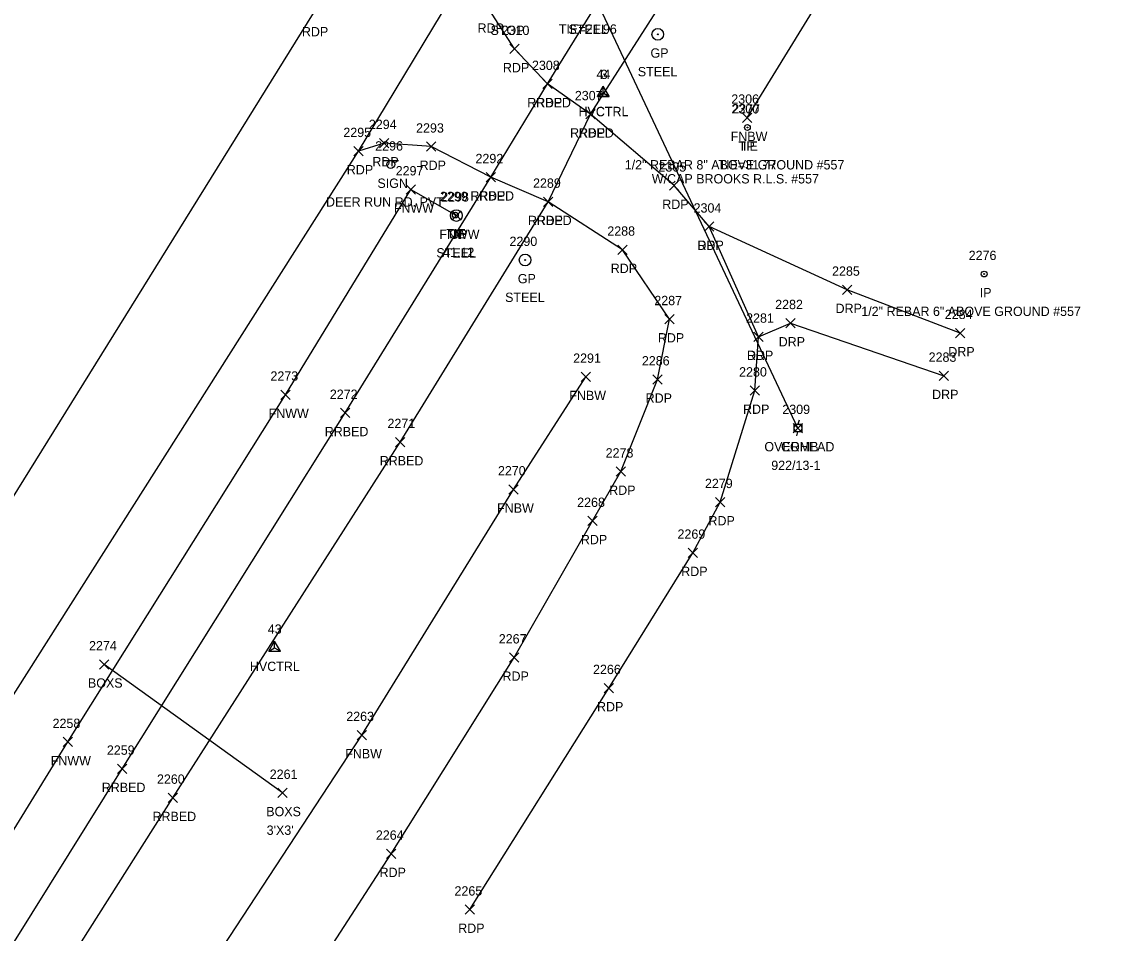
# Model space of a CAD drawing. Extents: x 1508122 to 1515053, y 865012 to 875267.
# Drawn here: x 1513728.5 to 1513963.5, y 873540.6 to 873736 of the extents above; entities that cross this region are included whole.
import ezdxf

# ---------------------------------------------------------------- set-up
doc = ezdxf.new("R2010")
doc.units = 0
for name, color, linetype in [('C_A', 7, 'Continuous'), ('C_C', 7, 'Continuous'), ('C_I', 7, 'Continuous'), ('CBP', 7, 'Continuous'), ('CPSM', 7, 'Continuous'), ('D_A', 7, 'Continuous'), ('D_C', 7, 'Continuous'), ('D_I', 7, 'Continuous'), ('D_TIC', 7, 'Continuous'), ('DDEFAULT', 7, 'Continuous'), ('L_A', 7, 'Continuous'), ('L_I', 7, 'Continuous'), ('L_TIC', 7, 'Continuous'), ('LFNC', 7, 'Continuous'), ('M_A', 7, 'Continuous'), ('M_C', 7, 'Continuous'), ('M_I', 7, 'Continuous'), ('MPIR', 7, 'Continuous'), ('P_A', 7, 'Continuous'), ('P_I', 7, 'Continuous'), ('P_TIC', 7, 'Continuous'), ('PET', 7, 'Continuous'), ('R_A', 7, 'Continuous'), ('R_C', 7, 'Continuous'), ('R_I', 7, 'Continuous'), ('R_TIC', 7, 'Continuous'), ('RDP', 7, 'Continuous'), ('RGP', 7, 'Continuous'), ('RRB', 7, 'Continuous'), ('S_A', 7, 'Continuous'), ('S_C', 7, 'Continuous'), ('S_I', 7, 'Continuous'), ('SSGN', 7, 'Continuous'), ('U_A', 7, 'Continuous'), ('U_C', 7, 'Continuous'), ('U_I', 7, 'Continuous'), ('U_TIC', 7, 'Continuous'), ('UP', 7, 'Continuous'), ('UT', 7, 'Continuous')]:
    doc.layers.add(name, color=color, linetype=linetype)

msp = doc.modelspace()

# ---------------------------------------------------------------- linework, layer by layer
at = {"layer": 'CBP'}
for centre, radius in [((1513884.03, 873713.34), 0.625), ((1513884.03, 873713.34), 0.0833), ((1513821.41, 873694.56), 0.625), ((1513821.41, 873694.56), 0.0833)]:
    msp.add_circle(centre, radius, dxfattribs=at)
at = {"layer": 'CPSM'}
for p, q in [((1513851.88, 873720.05), (1513853.13, 873722.21)), ((1513851.88, 873720.01), (1513853.13, 873722.18)), ((1513854.38, 873720.05), (1513853.13, 873722.21)), ((1513853.13, 873720.77), (1513853.13, 873722.21)), ((1513854.38, 873720.01), (1513853.13, 873722.18)), ((1513853.13, 873720.73), (1513853.13, 873722.18)), ((1513851.88, 873720.05), (1513853.13, 873720.77)), ((1513851.88, 873720.01), (1513853.13, 873720.73)), ((1513851.88, 873720.05), (1513854.38, 873720.05)), ((1513851.88, 873720.01), (1513854.38, 873720.01)), ((1513853.13, 873720.77), (1513853.13, 873720.77)), ((1513853.13, 873720.77), (1513854.38, 873720.05)), ((1513853.13, 873720.73), (1513853.13, 873720.73)), ((1513853.13, 873720.73), (1513854.38, 873720.01)), ((1513781.42, 873601.07), (1513782.67, 873603.23)), ((1513783.92, 873601.07), (1513782.67, 873603.23)), ((1513782.67, 873601.79), (1513782.67, 873603.23)), ((1513781.42, 873601.07), (1513782.67, 873601.79)), ((1513781.42, 873601.07), (1513783.92, 873601.07)), ((1513782.67, 873601.79), (1513782.67, 873601.79)), ((1513782.67, 873601.79), (1513783.92, 873601.07))]:
    msp.add_line(p, q, dxfattribs=at)
at = {"layer": 'D_TIC'}
for points in [[(1513745.14, 873597.23), (1513747.14, 873599.23)], [(1513747.14, 873597.23), (1513745.14, 873599.23)], [(1513783.36, 873569.67), (1513785.36, 873571.67)], [(1513785.36, 873569.67), (1513783.36, 873571.67)]]:
    msp.add_lwpolyline(points, dxfattribs=at)
at = {"layer": 'DDEFAULT'}
msp.add_lwpolyline([(1513784.36, 873570.67), (1513746.14, 873598.23)], dxfattribs=at)
at = {"layer": 'L_TIC'}
for points in [[(1513882.96, 873714.43), (1513884.96, 873716.43)], [(1513884.96, 873714.43), (1513882.96, 873716.43)], [(1513810.88, 873699.06), (1513812.88, 873701.06)], [(1513812.88, 873699.06), (1513810.88, 873701.06)], [(1513820.63, 873693.46), (1513822.63, 873695.46)], [(1513822.63, 873693.46), (1513820.63, 873695.46)], [(1513848.36, 873658.88), (1513850.36, 873660.88)], [(1513850.36, 873658.88), (1513848.36, 873660.88)], [(1513784.03, 873655.05), (1513786.03, 873657.05)], [(1513786.03, 873655.05), (1513784.03, 873657.05)], [(1513832.88, 873634.74), (1513834.88, 873636.74)], [(1513834.88, 873634.74), (1513832.88, 873636.74)], [(1513800.33, 873582.07), (1513802.33, 873584.07)], [(1513802.33, 873582.07), (1513800.33, 873584.07)], [(1513737.32, 873580.58), (1513739.32, 873582.58)], [(1513739.32, 873580.58), (1513737.32, 873582.58)]]:
    msp.add_lwpolyline(points, dxfattribs=at)
at = {"layer": 'LFNC'}
for points in [[(1513883.96, 873715.43), (1513940.11, 873806.81), (1513990.41, 873887.15)], [(1513218.01, 872682.67), (1513239.79, 872733.41), (1513260.59, 872779.32), (1513279.8, 872820.34), (1513309.34, 872879.26), (1513337.46, 872931.88), (1513364.68, 872976.76), (1513384.37, 873008.89), (1513425.94, 873076.78), (1513474.35, 873155.62), (1513492.34, 873185.42), (1513532.61, 873250.79), (1513565.82, 873304.9), (1513599.41, 873358.19), (1513608.93, 873372.42), (1513641.55, 873425.64), (1513687.17, 873499.06), (1513712.19, 873539.19), (1513738.32, 873581.58), (1513785.03, 873656.05), (1513811.88, 873700.06), (1513821.63, 873694.46)], [(1513422.18, 872973.96), (1513469.32, 873050.55), (1513492.37, 873088.08), (1513518.11, 873128.09), (1513536.42, 873156.9), (1513559.84, 873194.99), (1513607.97, 873274.08), (1513649.94, 873340.43), (1513686.06, 873398.91), (1513733.34, 873474.67), (1513756.79, 873511.95), (1513770.19, 873535.54), (1513801.33, 873583.07), (1513833.88, 873635.74), (1513849.36, 873659.88)]]:
    msp.add_lwpolyline(points, dxfattribs=at)
at = {"layer": 'MPIR'}
for centre, radius in [((1513884.03, 873713.34), 0.625), ((1513884.03, 873713.34), 0.0833), ((1513934.79, 873681.92), 0.625), ((1513934.79, 873681.92), 0.0833)]:
    msp.add_circle(centre, radius, dxfattribs=at)
at = {"layer": 'P_TIC'}
for points in [[(1513833.12, 873729.17), (1513835.12, 873731.17)], [(1513835.12, 873729.17), (1513833.12, 873731.17)], [(1513840.18, 873721.67), (1513842.18, 873723.67)], [(1513842.18, 873721.67), (1513840.18, 873723.67)], [(1513849.37, 873715.18), (1513851.37, 873717.18)], [(1513851.37, 873715.18), (1513849.37, 873717.18)], [(1513805.13, 873709), (1513807.13, 873711)], [(1513807.13, 873709), (1513805.13, 873711)], [(1513815.26, 873708.24), (1513817.26, 873710.24)], [(1513817.26, 873708.24), (1513815.26, 873710.24)], [(1513799.66, 873707.29), (1513801.66, 873709.29)], [(1513801.66, 873707.29), (1513799.66, 873709.29)], [(1513799.66, 873707.29), (1513801.66, 873709.29)], [(1513801.66, 873707.29), (1513799.66, 873709.29)], [(1513827.99, 873701.68), (1513829.99, 873703.68)], [(1513829.99, 873701.68), (1513827.99, 873703.68)], [(1513867.29, 873699.88), (1513869.29, 873701.88)], [(1513869.29, 873699.88), (1513867.29, 873701.88)], [(1513840.33, 873696.41), (1513842.33, 873698.41)], [(1513842.33, 873696.41), (1513840.33, 873698.41)], [(1513874.83, 873691.09), (1513876.83, 873693.09)], [(1513876.83, 873691.09), (1513874.83, 873693.09)], [(1513856.25, 873686.14), (1513858.25, 873688.14)], [(1513858.25, 873686.14), (1513856.25, 873688.14)], [(1513866.33, 873671.24), (1513868.33, 873673.24)], [(1513868.33, 873671.24), (1513866.33, 873673.24)], [(1513885.44, 873667.48), (1513887.44, 873669.48)], [(1513887.44, 873667.48), (1513885.44, 873669.48)], [(1513863.72, 873658.32), (1513865.72, 873660.32)], [(1513865.72, 873658.32), (1513863.72, 873660.32)], [(1513884.6, 873655.94), (1513886.6, 873657.94)], [(1513886.6, 873655.94), (1513884.6, 873657.94)], [(1513855.9, 873638.57), (1513857.9, 873640.57)], [(1513857.9, 873638.57), (1513855.9, 873640.57)], [(1513877.19, 873632.02), (1513879.19, 873634.02)], [(1513879.19, 873632.02), (1513877.19, 873634.02)], [(1513849.83, 873627.98), (1513851.83, 873629.98)], [(1513851.83, 873627.98), (1513849.83, 873629.98)], [(1513871.35, 873621.16), (1513873.35, 873623.16)], [(1513873.35, 873621.16), (1513871.35, 873623.16)], [(1513833.03, 873598.7), (1513835.03, 873600.7)], [(1513835.03, 873598.7), (1513833.03, 873600.7)], [(1513853.29, 873592.15), (1513855.29, 873594.15)], [(1513855.29, 873592.15), (1513853.29, 873594.15)], [(1513806.68, 873556.62), (1513808.68, 873558.62)], [(1513808.68, 873556.62), (1513806.68, 873558.62)], [(1513823.54, 873544.65), (1513825.54, 873546.65)], [(1513825.54, 873544.65), (1513823.54, 873546.65)]]:
    msp.add_lwpolyline(points, dxfattribs=at)
at = {"layer": 'PET'}
for points in [[(1513466.17, 873213.07), (1513500.31, 873271.08), (1513533.51, 873325.85), (1513565.92, 873377.51), (1513601.02, 873434.43), (1513630.8, 873481.59), (1513663.12, 873532.69), (1513695.04, 873583.32), (1513791.03, 873737.88), (1513811.04, 873770.52), (1513826.41, 873795.21), (1513862.7, 873855.82), (1513892.11, 873904.49), (1513923.1, 873954.81)], [(1513455.04, 873151.27), (1513485.29, 873202.33), (1513519.6, 873259.87), (1513551.9, 873312.77), (1513584.37, 873365.63), (1513617.09, 873418.81), (1513648.76, 873468.83), (1513681.49, 873520.59), (1513713.49, 873570.94), (1513800.66, 873708.29), (1513826.54, 873751.18), (1513852.76, 873793.88), (1513881.72, 873842.17), (1513911.67, 873891.89), (1513942.82, 873942.89)], [(1513824.54, 873545.65), (1513854.29, 873593.15), (1513872.35, 873622.16), (1513878.19, 873633.02), (1513885.6, 873656.94), (1513886.44, 873668.48), (1513875.83, 873692.09), (1513868.29, 873700.88), (1513850.37, 873716.18), (1513841.18, 873722.67), (1513834.12, 873730.17), (1513828.68, 873738.66), (1513826.54, 873751.18)], [(1513618.36, 873267.88), (1513664.43, 873331.28), (1513701.45, 873388.1), (1513749.56, 873465.53), (1513781.18, 873516.7), (1513807.68, 873557.62), (1513834.03, 873599.7), (1513850.83, 873628.98), (1513856.9, 873639.57), (1513864.72, 873659.32), (1513867.33, 873672.24), (1513857.25, 873687.14), (1513841.33, 873697.41), (1513828.99, 873702.68), (1513816.26, 873709.24), (1513806.13, 873710), (1513800.66, 873708.29)]]:
    msp.add_lwpolyline(points, dxfattribs=at)
at = {"layer": 'R_TIC'}
for points in [[(1513840.18, 873721.67), (1513842.18, 873723.67)], [(1513842.18, 873721.67), (1513840.18, 873723.67)], [(1513849.37, 873715.18), (1513851.37, 873717.18)], [(1513851.37, 873715.18), (1513849.37, 873717.18)], [(1513827.99, 873701.68), (1513829.99, 873703.68)], [(1513829.99, 873701.68), (1513827.99, 873703.68)], [(1513840.33, 873696.41), (1513842.33, 873698.41)], [(1513842.33, 873696.41), (1513840.33, 873698.41)], [(1513874.83, 873691.09), (1513876.83, 873693.09)], [(1513876.83, 873691.09), (1513874.83, 873693.09)], [(1513904.44, 873677.55), (1513906.44, 873679.55)], [(1513906.44, 873677.55), (1513904.44, 873679.55)], [(1513892.24, 873670.39), (1513894.24, 873672.39)], [(1513894.24, 873670.39), (1513892.24, 873672.39)], [(1513928.61, 873668.27), (1513930.61, 873670.27)], [(1513930.61, 873668.27), (1513928.61, 873670.27)], [(1513885.44, 873667.48), (1513887.44, 873669.48)], [(1513887.44, 873667.48), (1513885.44, 873669.48)], [(1513925.14, 873659.1), (1513927.14, 873661.1)], [(1513927.14, 873659.1), (1513925.14, 873661.1)], [(1513796.76, 873651.14), (1513798.76, 873653.14)], [(1513798.76, 873651.14), (1513796.76, 873653.14)], [(1513808.55, 873644.89), (1513810.55, 873646.89)], [(1513810.55, 873644.89), (1513808.55, 873646.89)], [(1513748.97, 873574.84), (1513750.97, 873576.84)], [(1513750.97, 873574.84), (1513748.97, 873576.84)], [(1513759.83, 873568.62), (1513761.83, 873570.62)], [(1513761.83, 873568.62), (1513759.83, 873570.62)]]:
    msp.add_lwpolyline(points, dxfattribs=at)
at = {"layer": 'RDP'}
for points in [[(1513929.61, 873669.27), (1513905.44, 873678.55), (1513875.83, 873692.09)], [(1513886.44, 873668.48), (1513893.24, 873671.39), (1513926.14, 873660.1)]]:
    msp.add_lwpolyline(points, dxfattribs=at)
at = {"layer": 'RGP'}
for p, q in [((1513864.82, 873733.31), (1513864.82, 873733.31)), ((1513821.63, 873694.46), (1513821.63, 873694.46)), ((1513836.37, 873684.93), (1513836.37, 873684.93))]:
    msp.add_line(p, q, dxfattribs=at)
for centre, radius in [((1513864.82, 873733.31), 1.25), ((1513864.82, 873733.31), 0.0833), ((1513821.63, 873694.46), 1.25), ((1513821.63, 873694.46), 0.0833), ((1513836.37, 873684.93), 1.25), ((1513836.37, 873684.93), 0.0833)]:
    msp.add_circle(centre, radius, dxfattribs=at)
at = {"layer": 'RRB'}
for points in [[(1513228.31, 872677.99), (1513247.91, 872725.05), (1513270.86, 872775.34), (1513289.12, 872813.81), (1513319.1, 872873.87), (1513347.47, 872925.52), (1513374.77, 872971.44), (1513393.49, 873000.11), (1513437.27, 873071.02), (1513458.13, 873103.89), (1513504.32, 873179.38), (1513525.85, 873213.8), (1513574, 873293.73), (1513619.17, 873366.93), (1513650.95, 873417.63), (1513697.43, 873492.91), (1513723.07, 873532.74), (1513749.97, 873575.84), (1513797.76, 873652.14), (1513828.99, 873702.68), (1513841.18, 873722.67), (1513905.39, 873826.67), (1513957.69, 873911.9), (1513997.47, 873975.73)], [(1513240.34, 872672.59), (1513259.24, 872718.12), (1513282.12, 872769.92), (1513300.61, 872809.77), (1513331.29, 872869.64), (1513358.47, 872918.38), (1513387.89, 872964.97), (1513404.26, 872991.91), (1513448.93, 873064.4), (1513469.17, 873096.67), (1513514.98, 873172.69), (1513538.39, 873208.28), (1513585.22, 873287.66), (1513630.12, 873359.27), (1513661.28, 873410.15), (1513709.31, 873487.04), (1513733.32, 873526.23), (1513760.83, 873569.62), (1513809.55, 873645.89), (1513841.33, 873697.41), (1513850.37, 873716.18), (1513916.81, 873819.88), (1513968.56, 873904.51), (1514007.95, 873968.59)]]:
    msp.add_lwpolyline(points, dxfattribs=at)
at = {"layer": 'SSGN'}
for p, q in [((1513805.92, 873706.25), (1513809.25, 873706.25)), ((1513807.57, 873705.41), (1513807.57, 873705.41))]:
    msp.add_line(p, q, dxfattribs=at)
msp.add_circle((1513807.57, 873705.41), 0.833, dxfattribs=at)
at = {"layer": 'U_TIC'}
for points in [[(1513893.86, 873647.9), (1513895.86, 873649.9)], [(1513895.86, 873647.9), (1513893.86, 873649.9)]]:
    msp.add_lwpolyline(points, dxfattribs=at)
at = {"layer": 'UP'}
for p, q in [((1513894.02, 873648.07), (1513894.02, 873649.73)), ((1513894.02, 873649.73), (1513895.69, 873649.73)), ((1513895.11, 873650.57), (1513894.86, 873649.73)), ((1513895.69, 873649.73), (1513895.69, 873648.07)), ((1513895.69, 873648.07), (1513894.02, 873648.07)), ((1513894.61, 873647.23), (1513894.86, 873648.07)), ((1513894.86, 873648.9), (1513894.86, 873648.9))]:
    msp.add_line(p, q, dxfattribs=at)
msp.add_circle((1513894.86, 873648.9), 0.833, dxfattribs=at)
at = {"layer": 'UT'}
msp.add_lwpolyline([(1513894.86, 873648.9), (1513821.97, 873803.81)], dxfattribs=at)

# ---------------------------------------------------------------- texts
at = {"layer": 'C_A'}
for s, p in [('HVCTRL', (1513847.82, 873715.77)), ('HVCTRL', (1513847.82, 873715.73)), ('TIE', (1513882.11, 873708.34)), ('TIE', (1513819.49, 873689.56)), ('HVCTRL', (1513777.36, 873596.79))]:
    msp.add_text(s, height=2, dxfattribs=at).set_placement(p)
at = {"layer": 'C_C'}
for s, p in [('TIE=21.96', (1513843.61, 873733.45)), ('TIE=31.77', (1513877.82, 873704.34)), ('41.12', (1513818.79, 873685.56))]:
    msp.add_text(s, height=2, dxfattribs=at).set_placement(p)
at = {"layer": 'C_I'}
for s, p in [('44', (1513851.67, 873723.77)), ('3', (1513852.56, 873723.73)), ('2300', (1513880.6, 873716.34)), ('2299', (1513818.14, 873697.56)), ('43', (1513781.2, 873604.79))]:
    msp.add_text(s, height=2, dxfattribs=at).set_placement(p)
at = {"layer": 'D_A'}
for p in [(1513742.64, 873593.23), (1513780.87, 873565.67)]:
    msp.add_text('BOXS', height=2, dxfattribs=at).set_placement(p)
at = {"layer": 'D_C'}
msp.add_text("3'X3'", height=2, dxfattribs=at).set_placement((1513780.96, 873561.67))
at = {"layer": 'D_I'}
for s, p in [('2274', (1513742.88, 873601.23)), ('2261', (1513781.62, 873573.67))]:
    msp.add_text(s, height=2, dxfattribs=at).set_placement(p)
at = {"layer": 'L_A'}
for s, p in [('FNBW', (1513880.44, 873710.43)), ('FNWW', (1513808.23, 873695.06)), ('FNWW', (1513817.98, 873689.46)), ('FNBW', (1513845.84, 873654.88)), ('FNWW', (1513781.38, 873651.05)), ('FNBW', (1513830.36, 873630.74)), ('FNWW', (1513734.67, 873576.58)), ('FNBW', (1513797.8, 873578.07))]:
    msp.add_text(s, height=2, dxfattribs=at).set_placement(p)
at = {"layer": 'L_I'}
for s, p in [('2306', (1513880.57, 873718.43)), ('2297', (1513808.62, 873703.06)), ('2298', (1513818.37, 873697.46)), ('2291', (1513846.67, 873662.88)), ('2273', (1513781.77, 873659.05)), ('2270', (1513830.54, 873638.74)), ('2263', (1513798.02, 873586.07)), ('2258', (1513735.06, 873584.58))]:
    msp.add_text(s, height=2, dxfattribs=at).set_placement(p)
at = {"layer": 'M_A'}
for p in [(1513883.08, 873708.34), (1513933.84, 873676.92)]:
    msp.add_text('IP', height=2, dxfattribs=at).set_placement(p)
at = {"layer": 'M_C'}
for s, p in [('1/2" REBAR 8" ABOVE GROUND #557', (1513857.73, 873704.34)), ('W/CAP BROOKS R.L.S. #557', (1513863.54, 873701.34)), ('1/2" REBAR 6" ABOVE GROUND #557', (1513908.44, 873672.92))]:
    msp.add_text(s, height=2, dxfattribs=at).set_placement(p)
at = {"layer": 'M_I'}
for s, p in [('2277', (1513880.77, 873716.34)), ('2276', (1513931.47, 873684.92))]:
    msp.add_text(s, height=2, dxfattribs=at).set_placement(p)
at = {"layer": 'P_A'}
for p in [(1513788.52, 873732.88), (1513826.17, 873733.66), (1513831.61, 873725.17), (1513838.67, 873717.67), (1513847.86, 873711.18), (1513803.62, 873705), (1513813.75, 873704.24), (1513798.14, 873703.29), (1513798.14, 873703.29), (1513826.47, 873697.68), (1513865.78, 873695.88), (1513838.82, 873692.41), (1513873.31, 873687.09), (1513854.73, 873682.14), (1513864.82, 873667.24), (1513883.93, 873663.48), (1513862.21, 873654.32), (1513883.09, 873651.94), (1513854.39, 873634.57), (1513875.68, 873628.02), (1513848.32, 873623.98), (1513869.84, 873617.16), (1513831.52, 873594.7), (1513851.78, 873588.15), (1513805.17, 873552.62), (1513822.02, 873540.65)]:
    msp.add_text('RDP', height=2, dxfattribs=at).set_placement(p)
at = {"layer": 'P_I'}
for s, p in [('2310', (1513831.34, 873733.17)), ('2308', (1513837.84, 873725.67)), ('2307', (1513847.03, 873719.18)), ('2294', (1513802.87, 873713)), ('2295', (1513797.4, 873711.29)), ('2295', (1513797.4, 873711.29)), ('2293', (1513813, 873712.24)), ('2292', (1513825.73, 873705.68)), ('2305', (1513864.96, 873703.88)), ('2289', (1513838.07, 873700.41)), ('2304', (1513872.49, 873695.09)), ('2288', (1513853.99, 873690.14)), ('2287', (1513864.07, 873675.24)), ('2281', (1513883.75, 873671.48)), ('2286', (1513861.4, 873662.32)), ('2280', (1513882.25, 873659.94)), ('2278', (1513853.64, 873642.57)), ('2279', (1513874.92, 873636.02)), ('2268', (1513847.53, 873631.98)), ('2269', (1513869.04, 873625.16)), ('2267', (1513830.72, 873602.7)), ('2266', (1513850.93, 873596.15)), ('2264', (1513804.37, 873560.62)), ('2265', (1513821.23, 873548.65))]:
    msp.add_text(s, height=2, dxfattribs=at).set_placement(p)
at = {"layer": 'R_A'}
for s, p in [('GP', (1513863.25, 873728.31)), ('RRBED', (1513836.83, 873717.67)), ('RRBED', (1513846.02, 873711.18)), ('RRBED', (1513824.63, 873697.68)), ('RRBED', (1513836.98, 873692.41)), ('GP', (1513820.06, 873689.46)), ('DRP', (1513873.31, 873687.09)), ('GP', (1513834.8, 873679.93)), ('DRP', (1513902.93, 873673.55)), ('DRP', (1513890.73, 873666.39)), ('DRP', (1513883.93, 873663.48)), ('DRP', (1513927.1, 873664.27)), ('DRP', (1513923.63, 873655.1)), ('RRBED', (1513793.41, 873647.14)), ('RRBED', (1513805.19, 873640.89)), ('RRBED', (1513745.61, 873570.84)), ('RRBED', (1513756.48, 873564.62))]:
    msp.add_text(s, height=2, dxfattribs=at).set_placement(p)
at = {"layer": 'R_C'}
for p in [(1513845.65, 873733.38), (1513860.53, 873724.31), (1513817.35, 873685.46), (1513832.08, 873675.93)]:
    msp.add_text('STEEL', height=2, dxfattribs=at).set_placement(p)
at = {"layer": 'R_I'}
for s, p in [('2308', (1513837.84, 873725.67)), ('2307', (1513847.03, 873719.18)), ('2292', (1513825.73, 873705.68)), ('2289', (1513838.07, 873700.41)), ('2298', (1513818.37, 873697.46)), ('2304', (1513872.49, 873695.09)), ('2290', (1513833.02, 873687.93)), ('2285', (1513902.18, 873681.55)), ('2282', (1513889.98, 873674.39)), ('2281', (1513883.75, 873671.48)), ('2284', (1513926.35, 873672.27)), ('2283', (1513922.88, 873663.1)), ('2272', (1513794.5, 873655.14)), ('2271', (1513806.86, 873648.89)), ('2259', (1513746.7, 873578.84)), ('2260', (1513757.44, 873572.62))]:
    msp.add_text(s, height=2, dxfattribs=at).set_placement(p)
at = {"layer": 'S_A'}
msp.add_text('SIGN', height=2, dxfattribs=at).set_placement((1513804.7, 873700.39))
at = {"layer": 'S_C'}
for s, p in [('STOP', (1513828.96, 873733.18)), ('DEER RUN RD. PVT', (1513793.68, 873696.39))]:
    msp.add_text(s, height=2, dxfattribs=at).set_placement(p)
at = {"layer": 'S_I'}
msp.add_text('2296', height=2, dxfattribs=at).set_placement((1513804.23, 873708.39))
at = {"layer": 'U_A'}
for s, p in [('OVERHEAD', (1513887.67, 873643.9)), ('COMB', (1513891.24, 873643.9))]:
    msp.add_text(s, height=2, dxfattribs=at).set_placement(p)
at = {"layer": 'U_C'}
msp.add_text('922/13-1', height=2, dxfattribs=at).set_placement((1513889.14, 873639.9))
at = {"layer": 'U_I'}
msp.add_text('2309', height=2, dxfattribs=at).set_placement((1513891.51, 873651.9))
msp.add_text('2309', height=2, dxfattribs=at).set_placement((1513891.51, 873651.9))

doc.saveas('drawing.dxf')
